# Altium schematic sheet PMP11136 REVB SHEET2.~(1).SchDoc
size 431 x 279 mm; Date: Not shown in title block; ApprovedBy: Not shown in title block; CheckedBy: Not shown in title block; Author: Not shown in title block; CompanyName: Not shown in title block; Engineer: Not shown in title block; Organization: Not shown in title block; Address1: Not shown in title block; Address2: Not shown in title block; Address3: Not shown in title block; Address4: Not shown in title block; DocumentNumber: 2; Revision: Use project parameter SCH_Rev; SheetNumber: 2; SheetTotal: 3; PageSetup: Record=PageOptions¦CenterHorizontal=True¦CenterVertical=True¦PrintScale=1.00¦XCorrection=1.00¦YCorrection=1.00¦PrintKind=0¦BorderSize=5000000¦LeftOffset=0¦BottomOffset=0¦Orientation=2¦PaperLength=1000¦PaperWidth=1000¦Scale=100¦PaperSource=15¦PrintQuality=600¦MediaType=1¦DitherType=10¦PaperKind=Letter¦PrintScaleMode=1
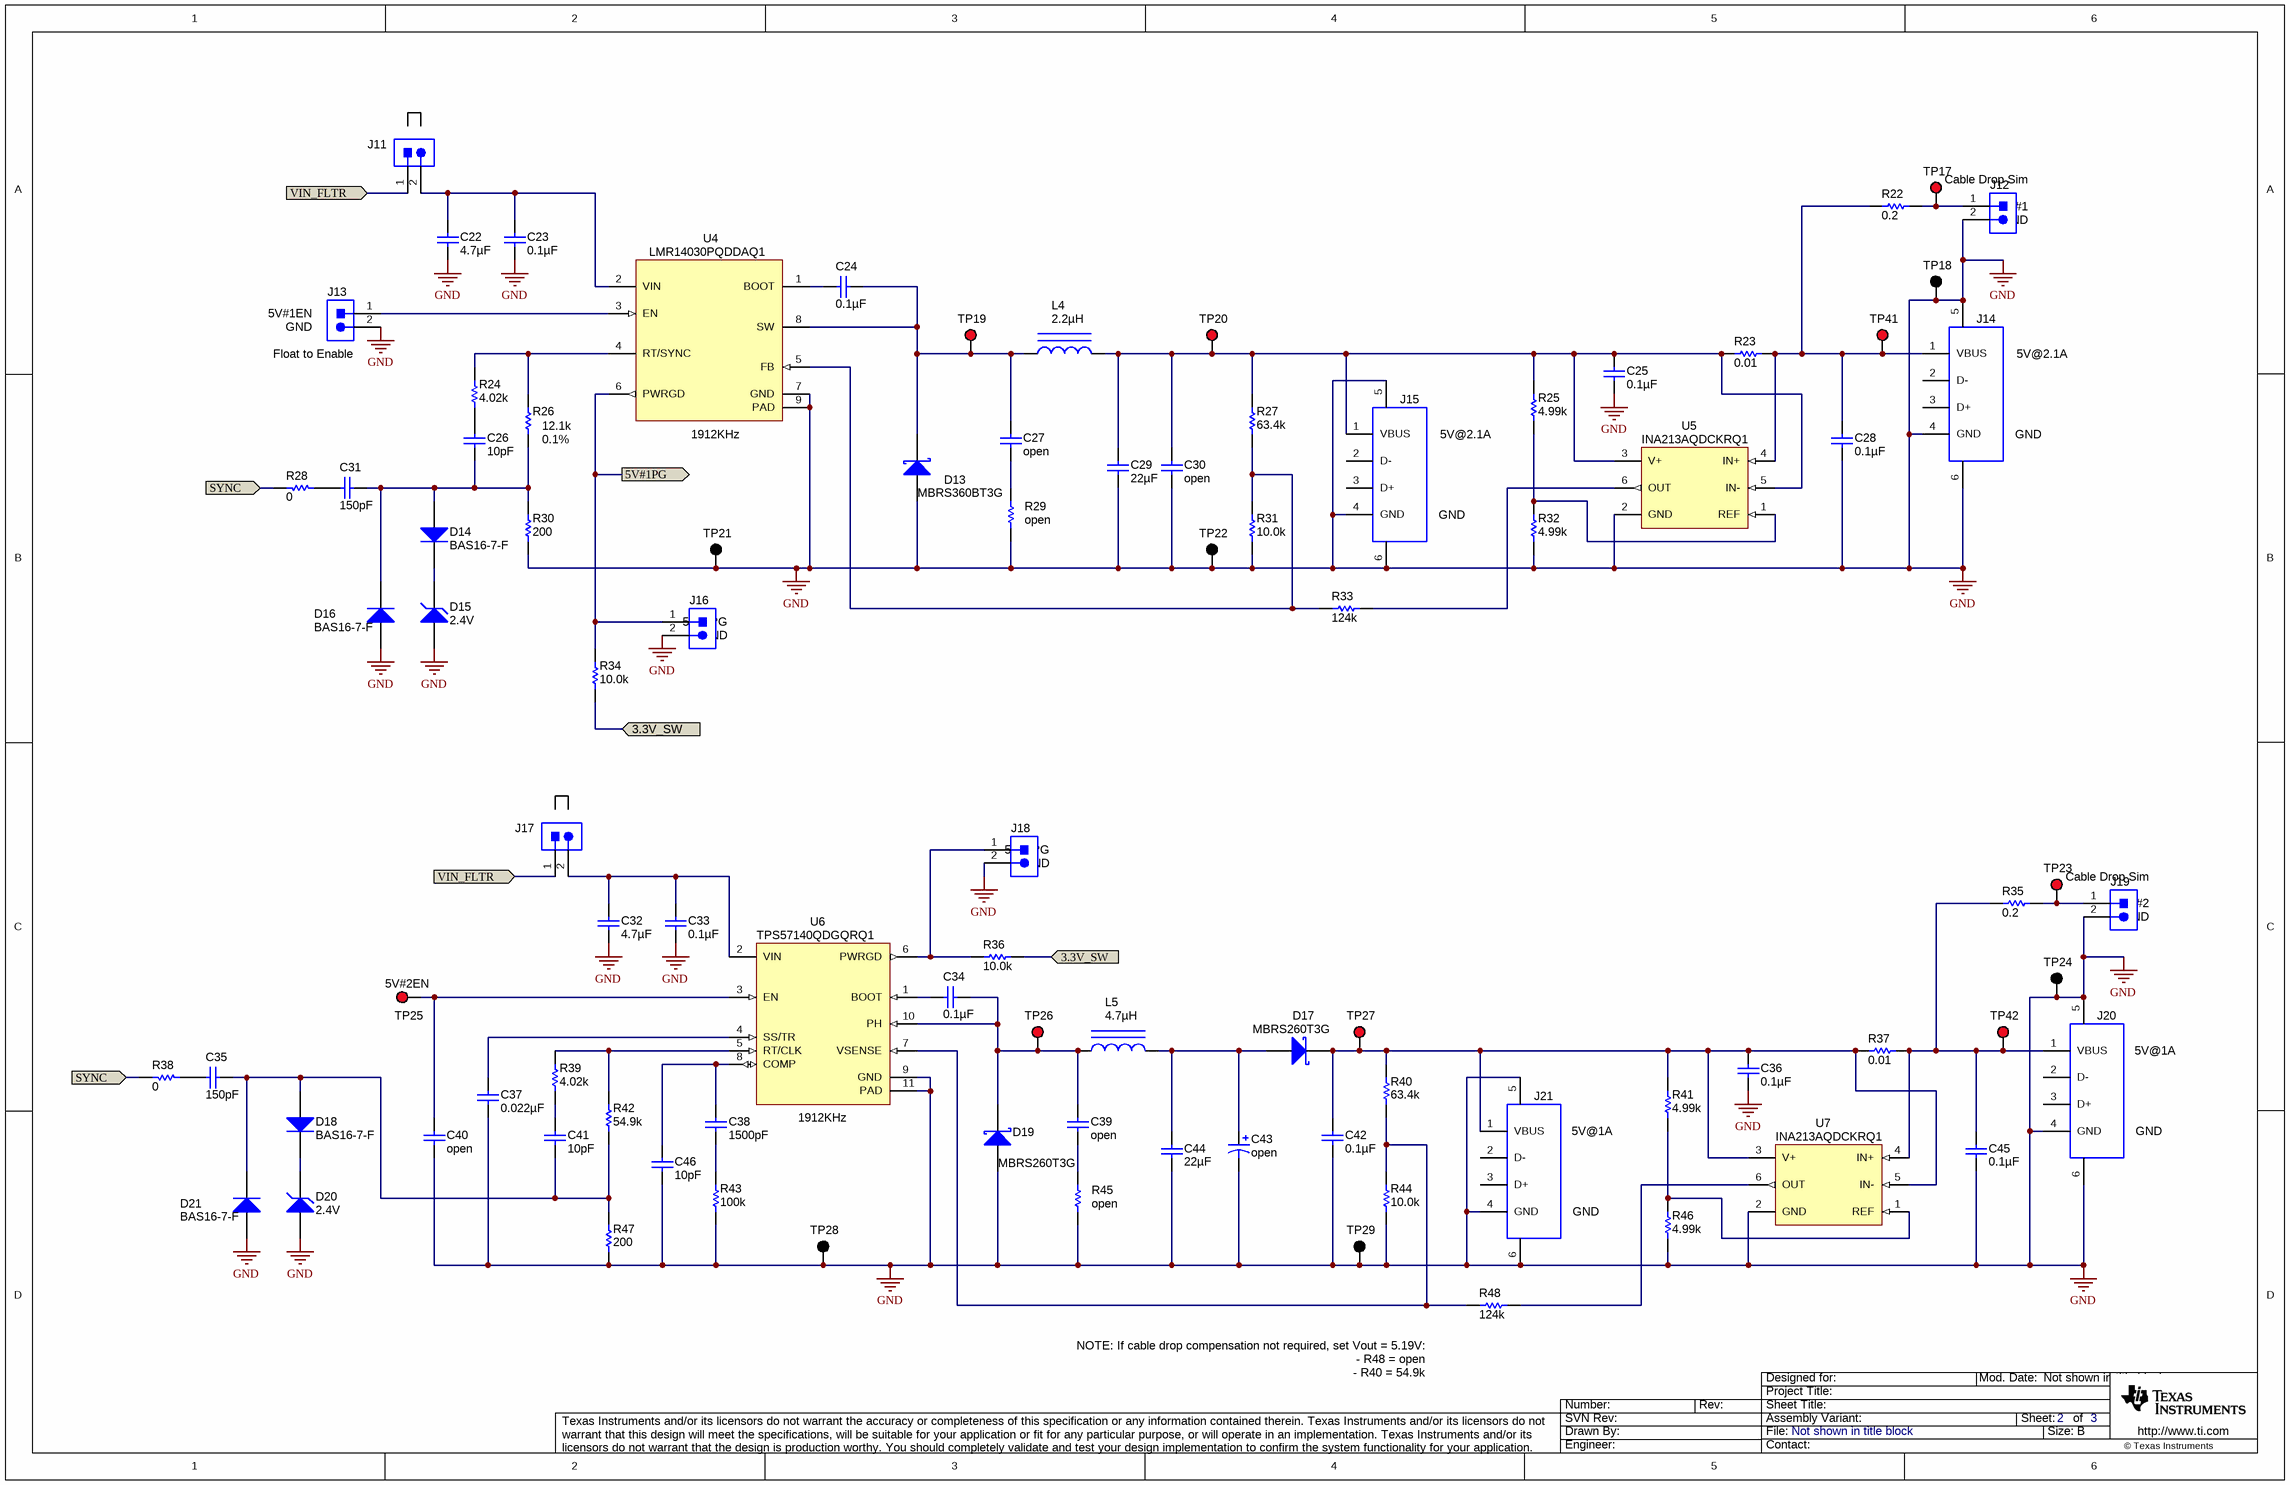
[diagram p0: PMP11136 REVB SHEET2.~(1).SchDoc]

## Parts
C22  ValueDisplayed: 4.7µF  [1210]  (hidden comment: C3225X7R1H475M250AB)
C23  ValueDisplayed: 0.1µF  [0603]  (hidden comment: C1608X7R1H104K)
C24  ValueDisplayed: 0.1µF  [0603]  (hidden comment: C1608X7R1H104K)
C25  ValueDisplayed: 0.1µF  [0402]  (hidden comment: C1005X7R1H104K050BB)
C26  ValueDisplayed: 10pF  [0603]  (hidden comment: C1608C0G1H100D)
C27  ValueDisplayed: open  [0603]
C28  ValueDisplayed: 0.1µF  [0402]  (hidden comment: C1005X7R1H104K050BB)
C29  ValueDisplayed: 22µF  [1210]  (hidden comment: C3225X7R1C226M250AC)
C30  ValueDisplayed: open  [1210]
C31  ValueDisplayed: 150pF  [0603]  (hidden comment: C1608C0G1H151J)
C32  ValueDisplayed: 4.7µF  [1210]  (hidden comment: C3225X7R1H475M250AB)
C33  ValueDisplayed: 0.1µF  [0603]  (hidden comment: C1608X7R1H104K)
C34  ValueDisplayed: 0.1µF  [0603]  (hidden comment: C1608X7R1H104K)
C35  ValueDisplayed: 150pF  [0603]  (hidden comment: C1608C0G1H151J)
C36  ValueDisplayed: 0.1µF  [0402]  (hidden comment: C1005X7R1H104K050BB)
C37  ValueDisplayed: 0.022µF  [0603]  (hidden comment: C1608X7R1H223K)
C38  ValueDisplayed: 1500pF  [0603]  (hidden comment: C1608C0G1H152J)
C39  ValueDisplayed: open  [0603]
C40  ValueDisplayed: open  [0603]
C41  ValueDisplayed: 10pF  [0603]  (hidden comment: C1608C0G1H100D)
C42  ValueDisplayed: 0.1µF  [0603]  (hidden comment: C1608X7R1H104K)
C43  ValueDisplayed: open  [7343-40]
C44  ValueDisplayed: 22µF  [1210]  (hidden comment: C3225X7R1C226M250AC)
C45  ValueDisplayed: 0.1µF  [0402]  (hidden comment: C1005X7R1H104K050BB)
C46  ValueDisplayed: 10pF  [0603]  (hidden comment: C1608C0G1H100D)
D13  MBRS360BT3G  [SMB]
D14  BAS16-7-F  [SOT-23]
D15  value 2.4V  [SOD-123]  (hidden comment: MMSZ5221B-7-F)
D16  BAS16-7-F  [SOT-23]
D17  MBRS260T3G  [SMB]
D18  BAS16-7-F  [SOT-23]
D19  MBRS260T3G  [SMB]
D20  value 2.4V  [SOD-123]  (hidden comment: MMSZ5221B-7-F)
D21  BAS16-7-F  [SOT-23]
J11  PEC02SAAN  [CONN_PEC02SAAN]  (value not drawn)
J12  PEC02SAAN  [CONN_PEC02SAAN]  (value not drawn)
J13  PEC02SAAN  [CONN_PEC02SAAN]  (value not drawn)
J14  676430910  [MOLEX_0676430910]  (value not drawn)
J15  676430910  [MOLEX_0676430910]  (value not drawn)
J16  PEC02SAAN  [CONN_PEC02SAAN]  (value not drawn)
J17  PEC02SAAN  [CONN_PEC02SAAN]  (value not drawn)
J18  PEC02SAAN  [CONN_PEC02SAAN]  (value not drawn)
J19  PEC02SAAN  [CONN_PEC02SAAN]  (value not drawn)
J20  676430910  [MOLEX_0676430910]  (value not drawn)
J21  676430910  [MOLEX_0676430910]  (value not drawn)
L4  ValueDisplayed: 2.2µH  [CLF6045NI-D]  (hidden comment: CLF6045NIT-2R2N-D)
L5  ValueDisplayed: 4.7µH  [CLF6045NI-D]  (hidden comment: CLF6045NIT-4R7N-D)
R22  ValueDisplayed: 0.2  [2512]  (hidden comment: CSRN2512FKR200)
R23  ValueDisplayed: 0.01  [1206]  (hidden comment: CSR1206FK10L0)
R24  ValueDisplayed: 4.02k  [0603]  (hidden comment: CRCW06034K02FKEA)
R25  ValueDisplayed: 4.99k  [0603]  (hidden comment: CRCW06034K99FKEA)
R26  Value1: 0.1%  ValueDisplayed: 12.1k  [0603]
R27  ValueDisplayed: 63.4k  [0603]  (hidden comment: CRCW060363K4FKEA)
R28  ValueDisplayed: 0  [0603]  (hidden comment: CRCW06030000Z0EA)
R29  value open  [2010]
R30  ValueDisplayed: 200  [0603]  (hidden comment: CRCW0603200RFKEA)
R31  ValueDisplayed: 10.0k  [0603]  (hidden comment: CRCW060310K0FKEA)
R32  ValueDisplayed: 4.99k  [0603]  (hidden comment: CRCW06034K99FKEA)
R33  ValueDisplayed: 124k  [0603]  (hidden comment: CRCW0603124KFKEA)
R34  ValueDisplayed: 10.0k  [0603]  (hidden comment: CRCW060310K0FKEA)
R35  ValueDisplayed: 0.2  [2512]  (hidden comment: CSRN2512FKR200)
R36  ValueDisplayed: 10.0k  [0603]  (hidden comment: CRCW060310K0FKEA)
R37  ValueDisplayed: 0.01  [1206]  (hidden comment: CSR1206FK10L0)
R38  ValueDisplayed: 0  [0603]  (hidden comment: CRCW06030000Z0EA)
R39  ValueDisplayed: 4.02k  [0603]  (hidden comment: CRCW06034K02FKEA)
R40  ValueDisplayed: 63.4k  [0603]  (hidden comment: CRCW060363K4FKEA)
R41  ValueDisplayed: 4.99k  [0603]  (hidden comment: CRCW06034K99FKEA)
R42  ValueDisplayed: 54.9k  [0603]  (hidden comment: CRCW060354K9FKEA)
R43  ValueDisplayed: 100k  [0603]  (hidden comment: CRCW0603100KFKEA)
R44  ValueDisplayed: 10.0k  [0603]  (hidden comment: CRCW060310K0FKEA)
R45  value open  [2010]
R46  ValueDisplayed: 4.99k  [0603]  (hidden comment: CRCW06034K99FKEA)
R47  ValueDisplayed: 200  [0603]  (hidden comment: CRCW0603200RFKEA)
R48  ValueDisplayed: 124k  [0603]  (hidden comment: CRCW0603124KFKEA)
TP17  5000  [Keystone5000]  (value not drawn)
TP18  5001  [Keystone5001]  (value not drawn)
TP19  5000  [Keystone5000]  (value not drawn)
TP20  5000  [Keystone5000]  (value not drawn)
TP21  5001  [Keystone5001]  (value not drawn)
TP22  5001  [Keystone5001]  (value not drawn)
TP23  5000  [Keystone5000]  (value not drawn)
TP24  5001  [Keystone5001]  (value not drawn)
TP25  5000  [Keystone5000]  (value not drawn)
TP26  5000  [Keystone5000]  (value not drawn)
TP27  5000  [Keystone5000]  (value not drawn)
TP28  5001  [Keystone5001]  (value not drawn)
TP29  5001  [Keystone5001]  (value not drawn)
TP41  5000  [Keystone5000]  (value not drawn)
TP42  5000  [Keystone5000]  (value not drawn)
U4  LMR14030PQDDAQ1  [DDA0008E_N]
U5  INA213AQDCKRQ1  [DCK0006A_N]
U6  TPS57140QDGQRQ1  [DGQ0010D_N]
U7  INA213AQDCKRQ1  [DCK0006A_N]

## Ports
3.3V_SW, 5V#1PG, SYNC, VIN_FLTR

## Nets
GND: C22.1 C23.2 C25.2 C28.2 C29.2 C30.2 C32.1 C33.2 C36.2 C37.2 C40.2 C42.2 C43.2(-) C44.2 C45.2 C46.2 D13.2(A) D15.2(A) D16.1(A) D19.2(A) D20.2(A) D21.1(A) J12.2 J13.2 J14.4(GND) J14.5(Shield) J14.6(Shield) J15.4(GND) J15.5(Shield) J15.6(Shield) J16.2 J18.2 J19.2 J20.4(GND) J20.5(Shield) J20.6(Shield) J21.4(GND) J21.5(Shield) J21.6(Shield) R29.1 R30.1 R31.1 R32.2 R43.1 R44.1 R45.1 R46.2 R47.1 TP18.1 TP21.1 TP22.1 TP24.1 TP28.1 TP29.1 U4.7(GND) U4.9(PAD) U5.2(GND) U6.9(GND) U6.11(PAD) U7.2(GND)
3.3V_SW: R34.1 R36.1 ; port 3.3V_SW
5V#1PG: J16.1 R34.2 U4.6(PWRGD) ; port 5V#1PG
SYNC: R28.1 R38.1 ; port SYNC
VIN_FLTR: J11.1 J17.1 ; port VIN_FLTR
NetC22_2: C22.2 C23.1 J11.2 U4.2(VIN)
NetC24_1: C24.1 U4.1(BOOT)
NetC24_2: C24.2 C27.1 D13.1(K) L4.1 TP19.1 U4.8(SW)
NetC25_1: C25.1 C29.1 C30.1 J15.1(VBUS) L4.2 R23.1 R25.1 R27.2 TP20.1 U5.3(V+) U5.5(IN-)
NetC26_1: C26.1 R24.2
NetC26_2: C26.2 C31.1 D14.1(A) D16.3(K) R26.1 R30.2
NetC27_2: C27.2 R29.2
NetC28_1: C28.1 J14.1(VBUS) R22.1 R23.2 TP41.1 U5.4(IN+)
NetC31_2: C31.2 R28.2
NetC32_2: C32.2 C33.1 J17.2 U6.2(VIN)
NetC34_1: C34.1 U6.1(BOOT)
NetC34_2: C34.2 C39.1 D19.1(K) L5.1 TP26.1 U6.10(PH)
NetC35_1: C35.1 C41.2 D18.1(A) D21.3(K) R42.1 R47.2
NetC35_2: C35.2 R38.2
NetC36_1: C36.1 C42.1 D17.1(K) J21.1(VBUS) R37.1 R40.2 R41.1 TP27.1 U7.3(V+) U7.5(IN-)
NetC37_1: C37.1 U6.4(SS/TR)
NetC38_1: C38.1 C46.1 U6.8(COMP)
NetC38_2: C38.2 R43.2
NetC39_2: C39.2 R45.2
NetC40_1: C40.1 TP25.1 U6.3(EN)
NetC41_1: C41.1 R39.2
NetC43_1: C43.1(+) C44.1 D17.2(A) L5.2
NetC45_1: C45.1 J20.1(VBUS) R35.1 R37.2 TP42.1 U7.4(IN+)
NetD14_3: D14.3(K) D15.1(K)
NetD18_3: D18.3(K) D20.1(K)
NetJ12_1: J12.1 R22.2 TP17.1
NetJ13_1: J13.1 U4.3(EN)
NetJ18_1: J18.1 R36.2 U6.6(PWRGD)
NetJ19_1: J19.1 R35.2 TP23.1
NetR24_1: R24.1 R26.2 U4.4(RT/SYNC)
NetR25_2: R25.2 R32.1 U5.1(REF)
NetR27_1: R27.1 R31.2 R33.2 U4.5(FB)
NetR33_1: R33.1 U5.6(OUT)
NetR39_1: R39.1 R42.2 U6.5(RT/CLK)
NetR40_1: R40.1 R44.2 R48.2 U6.7(VSENSE)
NetR41_2: R41.2 R46.1 U7.1(REF)
NetR48_1: R48.1 U7.6(OUT)

Not connected (* = marked no-connect by the designer): J14 2(D-) 3(D+); J15 2(D-) 3(D+); J20 2(D-) 3(D+); J21 2(D-) 3(D+)

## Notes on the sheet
- (near J12) 5V#1
- (near J12) GND
- (near J12) Cable Drop Sim
- (near J13) 5V#1EN
- (near J13) GND
- (near J13) Float to Enable
- 5V@2.1A
- (near U4) 1912KHz
- GND
- 5V#1PG
- (near J16) GND
- (near J18) 5V#2PG
- (near J18) GND
- (near J19) 5V#2
- (near J19) Cable Drop Sim
- (near J19) GND
- (near TP25) 5V#2EN
- 5V@1A
- (near U6) 1912KHz
- (near R48) NOTE: If cable drop compensation not required, set Vout = 5.19V:
- (near R48) - R48 = open
- - R40 = 54.9k

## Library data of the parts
C22 C32 = C3225X7R1E106M: CAP, CERM, 4.7uF, 50V, +/-20%, X7R, 1210; Manufacturer: TDK; Polarized: N; CompType: Capacitor; U/M: EA; Cap_F: 0.00001; Tolerance_%: 20; ESR_Ohm: 0.0027; Value1: 0.0027 ohm; VDC_V: 50; IRMS_A: 3; TaMin_C: -55; TaMax_C: 125
C23 C24 C33 C34 C42 = C1608X7R1H104K: CAP, CERM, 0.1uF, 50V, +/-10%, X7R, 0603; Manufacturer: TDK; Polarized: N; CompType: Capacitor; U/M: EA; Cap_F: 0.0000001; Tolerance_%: 10; ESR_Ohm: 0.017; Value1: 0.017 ohm; VDC_V: 50; TaMin_C: -55; TaMax_C: 125
C25 C28 C36 C45 = C1005X7R1H104K050BB: CAP, CERM, 0.1uF, 50V, +/-10%, X7R, 0402; Manufacturer: TDK; Polarized: N; CompType: Capacitor; U/M: EA; Cap_F: 0.0000001; Tolerance_%: 10; Value1: Unknown; VDC_V: 50; TaMin_C: -55; TaMax_C: 125
C26 C41 C46 = C1608C0G1H100D: CAP, CERM, 10 pF, 50 V, +/- 5%, C0G/NP0, 0603; Manufacturer: TDK; Polarized: N; CompType: Capacitor; Value: 10pF; U/M: EA; Cap_F: 0.00000000001; Tolerance_%: 5; ESR_ohm: 0.3492; Value1: 0.3492 ohm; VDC_V: 50; Value2: 50V; TaMin_C: -55; TaMax_C: 125
C27 C39 C40 = C1608C0G1H102J: CAP, CERM, open, 0603; Polarized: N; CompType: Capacitor; U/M: EA; Cap_F: 0.000000001; Tolerance_%: 5; ESR_ohm: 0.0563; TempCo: C0G/NP0; TaMin_C: -55; TaMax_C: 125
C29 C44 = C3225X7R1C226M: CAP, CERM, 22 µF, 16 V, +/- 20%, X7R, 1210; Manufacturer: TDK; Polarized: N; CompType: Capacitor; Value: 22uF; U/M: EA; Cap_F: 0.000022; Tolerance_%: 20; ESR_ohm: 0.002; Value1: 0.002 ohm; VDC_V: 16; Value2: 16V; IRMS_A: 8.11; TaMin_C: -55; TaMax_C: 125
C30 = C3225X7R1C226M: CAP, open, 1210; Polarized: N; CompType: Capacitor; U/M: EA; Cap_F: 0.000022; Tolerance_%: 20; ESR_ohm: 0.002; TempCo: X7R; IRMS_A: 8.11; TaMin_C: -55; TaMax_C: 125
C31 C35 = C1608C0G1H151J: CAP, CERM, 150 pF, 50 V, +/- 5%, C0G/NP0, 0603; Manufacturer: TDK; Polarized: N; CompType: Capacitor; Value: 150pF; U/M: EA; Cap_F: 0.00000000015; Tolerance_%: 5; ESR_ohm: 0.1084; Value1: 0.1084 ohm; VDC_V: 50; Value2: 50V; TaMin_C: -55; TaMax_C: 125
C37 = C1608X7R1H223K: CAP, CERM, 0.022 µF, 50 V, +/- 10%, X7R, 0603; Manufacturer: TDK; Polarized: N; CompType: Capacitor; Value: 0.022uF; U/M: EA; Cap_F: 0.000000022; Tolerance_%: 10; ESR_ohm: 0.0383; Value1: 0.0383 ohm; VDC_V: 50; Value2: 50V; TaMin_C: -55; TaMax_C: 125
C38 = C1608C0G1H152J: CAP, CERM, 1500 pF, 50 V, +/- 5%, C0G/NP0, 0603; Manufacturer: TDK; Polarized: N; CompType: Capacitor; Value: 1500pF; U/M: EA; Cap_F: 0.0000000015; Tolerance_%: 5; ESR_ohm: 0.039; Value1: 0.039 ohm; VDC_V: 50; Value2: 50V; TaMin_C: -55; TaMax_C: 125
C43 = 10TPB220M: CAP, open, 7343-40 SMD; Polarized: Y; CompType: Capacitor; U/M: EA; Cap_F: 0.00022; Tolerance_%: 20; ESR_ohm: 0.04; IRMS_A: 3; TaMin_C: -55; TaMax_C: 105; Cap_Case: D
D13 = MBRS260T3G: Diode, Schottky, 60V, 3A, SMB; Manufacturer: ON Semiconductor; U/M: EA; Vf_V: 0.63; Value2: 0.63V; Io_A: 2; Vr_V: 60; TJmax_C: 125; RJC_CperW: 24
D14 D16 D18 D21 = BAS16-7-F: Diode, Ultrafast, 75V, 0.3A, SOT-23; Manufacturer: Diodes Inc.; U/M: EA; Vf_V: 1.125; Value2: 1.125V; Io_A: 0.3; Vr_V: 75
D15 D20 = MMSZ5221B-7-F: Diode, Zener, 2.4V, 500 mW, SOD-123; Manufacturer: Diodes Inc.; SymbolCreator: a0412235; U/M: EA; Power_W: 0.5; Vz_V: 2.4; Value1: 0.5W; RJA_CperW: 350
D17 D19 = MBRS260T3G: Diode, Schottky, 60V, 2A, SMB; Manufacturer: ON Semiconductor; U/M: EA; Vf_V: 0.63; Value2: 0.63V; Io_A: 2; Vr_V: 60; TJmax_C: 125; RJC_CperW: 24
J11-J13 J16-J19 = PEC02SAAN: Header, 100mil, 2x1, Tin, TH; Manufacturer: Sullins Connector Solutions; SymbolCreator: a0412235; U/M: EA
J14 J15 J20 J21 = 676430910: Connector, Receptacle, USB Standard, R/A, Top Mount TH; Manufacturer: Molex; SymbolCreator: a0412235; U/M: EA
L4 = CLF6045NIT-2R2N-D: Inductor, Wirewound, Ferrite, 2.2 µH, 4.1 A, 0.015 ohm, SMD; Manufacturer: TDK; Value: 2.2uH; Ind_H: 2.2E-6; Imax_A: 4.1; Irms: 4.1A @ 40C rise; Isat: 4.2A @ 30% inductance drop; DCR_ohm: 0.015; Value2: 4.1A
L5 = CLF6045NIT-4R7N-D: Inductor, Wirewound, Ferrite, 4.7 µH, 3.1 A, 0.023 ohm, SMD; Manufacturer: TDK; Value: 4.7uH; Ind_H: 4.7E-6; Imax_A: 3.1; Irms: 3.3A @ 40C rise; Isat: 3.1A @ 30% inductance drop; DCR_ohm: 0.023; Value2: 3.1A
R22 R35 = CSRN2512FKR200: RES, 0.2, 1%, 2 W, 2512; Manufacturer: Stackpole Electronics Inc; CompType: Resistor; Value: 0.2; Value_Code: R200; Tolerance_%: 1; Power_W: 2; Value2: 2W; TempCo: 200 ppm/C; EIA_Code: E96; U/M: EA
R23 R37 = CSR1206FK10L0: RES, 0.01, 1%, 0.5 W, 1206; Manufacturer: Stackpole Electronics Inc; CompType: Resistor; Value: 0.01; Value_Code: R010; Tolerance_%: 1; Power_W: 0.5; Value2: 0.5W; TempCo: 100 ppm/C; EIA_Code: E96; U/M: EA
R24 R39 = CRCW06034K02FKEA: RES, 4.02 k, 1%, 0.1 W, 0603; Manufacturer: Vishay-Dale; CompType: Resistor; Value: 4.02k; Res_ohm: 4020; Value_Code: 4k02; Tolerance_%: 1; Power_W: 0.1; Value2: 0.1W; VDC_V: 75; TempCo: 100 ppm/C; EIA_Code: E96; U/M: EA
R25 R32 R41 R46 = CRCW06034K99FKEA: RES, 4.99 k, 1%, 0.1 W, 0603; Manufacturer: Vishay-Dale; CompType: Resistor; Value: 4.99k; Res_ohm: 4990; Value_Code: 4k99; Tolerance_%: 1; Power_W: 0.1; Value2: 0.1W; VDC_V: 75; TempCo: 100 ppm/C; EIA_Code: E96; U/M: EA
R26 = CRCW060312K1FKEA: RES, 12.1 k, 0.1%, 0.1 W, 0603; Manufacturer: Vishay-Dale; CompType: Resistor; Value: 12.1k; Res_ohm: 12100; Value_Code: 12k1; Tolerance_%: 1; Power_W: 0.1; Value2: 0.1W; VDC_V: 75; TempCo: 100 ppm/C; EIA_Code: E96; U/M: EA
R27 R40 = CRCW060363K4FKEA: RES, 63.4 k, 1%, 0.1 W, 0603; Manufacturer: Vishay-Dale; CompType: Resistor; Value: 63.4k; Res_ohm: 63400; Value_Code: 63k4; Tolerance_%: 1; Power_W: 0.1; Value2: 0.1W; VDC_V: 75; TempCo: 100 ppm/C; EIA_Code: E96; U/M: EA
R28 R38 = CRCW06030000Z0EA: RES, 0, 5%, 0.1 W, 0603; Manufacturer: Vishay-Dale; CompType: Resistor; Value: 0; Value_Code: 0000; Tolerance_%: 5; Power_W: 0.1; Value2: 0.1W; VDC_V: 75; TempCo: 200 ppm/C; EIA_Code: E24; U/M: EA
R29 R45 = CRCW20102R70JNEF: RES, open, 2010; CompType: Resistor; Tolerance_%: 5; Power_W: 0.75; TempCo: 200 ppm/C; EIA_Code: E24; U/M: EA
R30 R47 = CRCW0603200RFKEA: RES, 200, 1%, 0.1 W, 0603; Manufacturer: Vishay-Dale; CompType: Resistor; Value: 200; Value_Code: 200R; Tolerance_%: 1; Power_W: 0.1; Value2: 0.1W; VDC_V: 75; TempCo: 100 ppm/C; EIA_Code: E96; U/M: EA
R31 R34 R36 R44 = CRCW060310K0FKEA: RES, 10.0 k, 1%, 0.1 W, 0603; Manufacturer: Vishay-Dale; CompType: Resistor; Value: 10.0k; Res_ohm: 10000; Value_Code: 10k0; Tolerance_%: 1; Power_W: 0.1; Value2: 0.1W; VDC_V: 75; TempCo: 100 ppm/C; EIA_Code: E96; U/M: EA
R33 R48 = CRCW0603124KFKEA: RES, 124 k, 1%, 0.1 W, 0603; Manufacturer: Vishay-Dale; CompType: Resistor; Value: 124k; Res_ohm: 124000; Tolerance_%: 1; Power_W: 0.1; Value2: 0.1W; VDC_V: 75; TempCo: 100 ppm/C; EIA_Code: E96; U/M: EA
R42 = CRCW060354K9FKEA: RES, 54.9 k, 1%, 0.1 W, 0603; Manufacturer: Vishay-Dale; CompType: Resistor; Value: 54.9k; Res_ohm: 54900; Value_Code: 54k9; Tolerance_%: 1; Power_W: 0.1; Value2: 0.1W; VDC_V: 75; TempCo: 100 ppm/C; EIA_Code: E96; U/M: EA
R43 = CRCW0603100KFKEA: RES, 100 k, 1%, 0.1 W, 0603; Manufacturer: Vishay-Dale; CompType: Resistor; Value: 100k; Res_ohm: 100000; Tolerance_%: 1; Power_W: 0.1; Value2: 0.1W; VDC_V: 75; TempCo: 100 ppm/C; EIA_Code: E96; U/M: EA
TP17 TP19 TP20 TP23 TP25-TP27 TP41 TP42 = 5000: Test Point, Miniature, Red, TH; Manufacturer: Keystone; CompType: Test Point Loop; U/M: EA
TP18 TP21 TP22 TP24 TP28 TP29 = 5001: Test Point, Miniature, Black, TH; Manufacturer: Keystone; CompType: Test Point Loop; U/M: EA
U4 = LMR14030PDDAR: LMR14030PQDDAQ1, DDA0008E; Manufacturer: Texas Instruments; SymbolCreator: Altium; CompType: IC; U/M: EA
U5 U7 = INA213AIDCK: Voltage Output, High or Low Side Measurement, Bi-Directional Zero-Drift Series Current-Shunt Monitor, DCK0006A; Alternate Manufacturer: None; Manufacturer: Texas Instruments; SymbolCreator: a0411947; CompType: IC; U/M: EA
U6 = TPS57140QDGQRQ1: 1.5-A 42-V STEP-DOWN SWIFT DC-DC CONVERTER WITH Eco-mode CONTROL, DGQ0010D; Manufacturer: Texas Instruments; SymbolCreator: a0799628; CompType: IC; U/M: EA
